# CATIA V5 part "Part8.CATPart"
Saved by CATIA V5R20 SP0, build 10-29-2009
Part number: 1bola238
Revision: ANY
Definition: UNKNOWN
Nomenclature: 1bola238
Source: Unknown
Bounding box of the stored display mesh (mm): x -1.19 to 1.19, y -1.19 to 1.19, z -1.19 to 1.19
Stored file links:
  C:\Users\Utente\Desktop\IO LAVORO\3D X SITO CF\CUMSA\3D files BE\BE 041216\Part8.CATPart
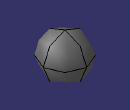
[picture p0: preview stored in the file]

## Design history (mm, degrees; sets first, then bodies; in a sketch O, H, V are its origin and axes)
Body1 "Revolución1" (main body)
  Solid1: solid without history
